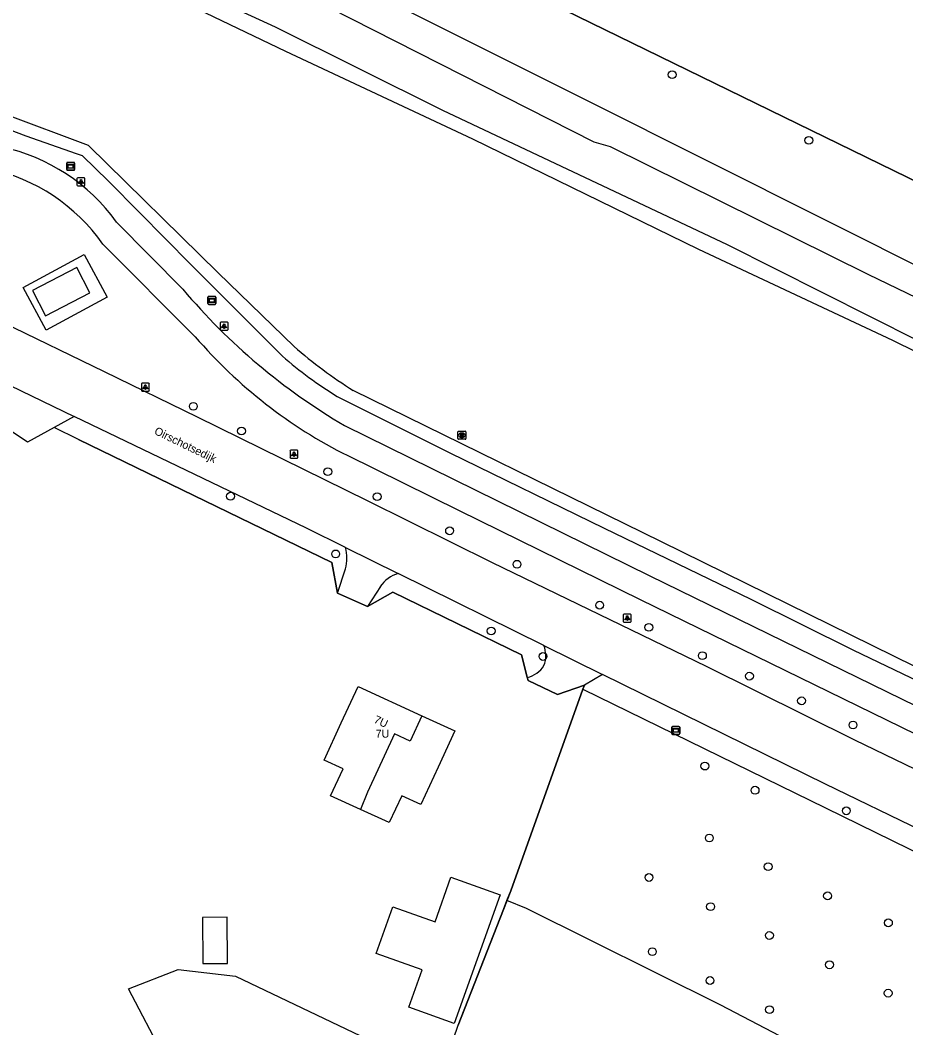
# Model space of a CAD drawing. Extents: x 156141 to 158132, y 385651 to 388399.
# Drawn here: x 156399.4 to 156510, y 386384.2 to 386510.1 of the extents above; entities that cross this region are included whole.
import ezdxf

# ---------------------------------------------------------------- set-up
doc = ezdxf.new("R2010")
doc.units = 0
for name, color, linetype in [('IMGEO_Berm_groen', 7, 'Continuous'), ('IMGEO_Boom', 7, 'Continuous'), ('IMGEO_Bouwland', 7, 'Continuous'), ('IMGEO_Fietspad_gesloten', 7, 'Continuous'), ('IMGEO_Grasland_overig', 7, 'Continuous'), ('IMGEO_Groenvoorziening', 7, 'Continuous'), ('IMGEO_Hek', 7, 'Continuous'), ('IMGEO_Lichtpunt', 7, 'Continuous'), ('IMGEO_Loofbos', 7, 'Continuous'), ('IMGEO_Openbare_ruimte_label', 7, 'Continuous'), ('IMGEO_Pand', 7, 'Continuous'), ('IMGEO_Pand_nummerreeks', 7, 'Continuous'), ('IMGEO_Rijbaan_lokaal_gesloten', 7, 'Continuous'), ('IMGEO_Rijbaan_lokaal_open', 7, 'Continuous'), ('IMGEO_Rioolput', 7, 'Continuous'), ('IMGEO_Verklikker', 7, 'Continuous'), ('IMGEO_Voetpad_open', 7, 'Continuous'), ('IMGEO_Waterloop', 7, 'Continuous')]:
    doc.layers.add(name, color=color, linetype=linetype)

msp = doc.modelspace()

# ---------------------------------------------------------------- linework, layer by layer
at = {"layer": 'IMGEO_Berm_groen'}
for points in [[(156439.05, 386438.5), (156438.33, 386442.3), (156406.68, 386457.7), (156403.63, 386459.18)], [(156462.74, 386427.97), (156462.02, 386430.79), (156445.93, 386438.62), (156442.77, 386436.8)], [(156469.7, 386426.47), (156469.88, 386426.98)], [(156469.7, 386426.47), (156500, 386411.64), (156522.94, 386400.43), (156557.16, 386383.7), (156598.54, 386363.27), (156625.35, 386349.27), (156637.95, 386342.17)]]:
    msp.add_lwpolyline(points, dxfattribs=at)
at = {"layer": 'IMGEO_Boom'}
for centre in [(156480.85, 386503.28), (156497.93, 386495.07), (156421.02, 386461.84), (156427.04, 386458.75), (156437.82, 386453.67), (156425.67, 386450.6), (156443.99, 386450.55), (156453.04, 386446.28), (156438.8, 386443.39), (156461.47, 386442.1), (156471.79, 386436.98), (156458.24, 386433.76), (156477.94, 386434.21), (156464.71, 386430.58), (156484.63, 386430.67), (156490.51, 386428.12), (156497.02, 386425.04), (156503.45, 386422.01), (156484.94, 386416.88), (156491.21, 386413.86), (156502.61, 386411.29), (156485.49, 386407.89), (156492.84, 386404.31), (156477.95, 386402.96), (156500.27, 386400.66), (156485.65, 386399.31), (156507.87, 386397.29), (156493.01, 386395.71), (156478.38, 386393.68), (156500.51, 386392.05), (156485.58, 386390.08), (156507.84, 386388.5), (156493.02, 386386.44)]:
    msp.add_circle(centre, 0.489, dxfattribs=at)
at = {"layer": 'IMGEO_Bouwland'}
msp.add_lwpolyline([(156417.37, 386380.55), (156412.91, 386389.03), (156419.13, 386391.45), (156426.28, 386390.61), (156452.01, 386378.34), (156453, 386381.23), (156454.11, 386384.49), (156459.32, 386397.81), (156459.77, 386398.95), (156460.2, 386400.06)], dxfattribs=at)
at = {"layer": 'IMGEO_Fietspad_gesloten'}
for points in [[(156411.43, 386484.87), (156419.73, 386476.46)], [(156421.26, 386470.53), (156409.71, 386482.11)], [(156439.93, 386459.43), (156478.08, 386440.66), (156748.12, 386308.63)], [(156746.83, 386305.79), (156476.91, 386437.66), (156454.28, 386448.77), (156440.3, 386455.67)]]:
    msp.add_lwpolyline(points, dxfattribs=at)
for centre, radius, start, end in [((156391.92, 386470.71), 24.11, 35.9629, 77.5317), ((156390.63, 386468.7), 23.33, 35.087, 77.7389), ((156479.24, 386526.56), 77.79, 220.0905, 239.6437), ((156467.78, 386510.52), 61.34, 220.6876, 243.3947)]:
    msp.add_arc(centre, radius, start, end, dxfattribs=at)
at = {"layer": 'IMGEO_Grasland_overig'}
for points in [[(156460.2, 386400.06), (156460.68, 386401.29), (156469.7, 386426.47)], [(156628.11, 386317.67), (156606.62, 386328.01), (156593.06, 386334.88), (156583.4, 386339.46), (156570.36, 386346.01), (156559.71, 386351.24), (156550.14, 386355.98), (156542.93, 386359.58), (156531.52, 386364.75), (156519.92, 386370.3), (156509.11, 386375.43), (156486.95, 386387.02), (156462.63, 386399.06), (156460.2, 386400.06)]]:
    msp.add_lwpolyline(points, dxfattribs=at)
at = {"layer": 'IMGEO_Groenvoorziening'}
for points in [[(156371.99, 386566.95), (156447.85, 386532.48), (156458.65, 386520.98), (156467.27, 386511.43), (156654.66, 386420.01), (156654.6, 386419.89), (156819.39, 386339.6), (156839.51, 386329.8), (156877.29, 386311.4)], [(156658.9, 386407.79), (156570.45, 386449.76), (156500, 386485.09), (156470.28, 386500), (156436.29, 386517.05)]]:
    msp.add_lwpolyline(points, dxfattribs=at)
at = {"layer": 'IMGEO_Hek'}
for points in [[(156654.66, 386420.01), (156467.27, 386511.43), (156458.65, 386520.98)], [(156406.68, 386457.7), (156438.33, 386442.3), (156439.05, 386438.5)], [(156439.05, 386438.5), (156442.77, 386436.8)], [(156442.77, 386436.8), (156445.93, 386438.62), (156462.02, 386430.79), (156462.74, 386427.97)], [(156462.74, 386427.97), (156462.84, 386427.57), (156466.54, 386425.84), (156469.88, 386426.98)], [(156469.7, 386426.47), (156460.68, 386401.29)], [(156469.88, 386426.98), (156469.7, 386426.47)], [(156460.68, 386401.29), (156459.77, 386398.95)], [(156459.77, 386398.95), (156454.11, 386384.49)]]:
    msp.add_lwpolyline(points, dxfattribs=at)
at = {"layer": 'IMGEO_Lichtpunt'}
for p, q in [((156406.48, 386490.3), (156406.48, 386489.5)), ((156406.48, 386490.3), (156406.48, 386489.5)), ((156407.38, 386490.4), (156406.57, 386490.4)), ((156407.38, 386490.4), (156406.57, 386490.4)), ((156407.48, 386489.5), (156407.48, 386490.3)), ((156407.48, 386489.5), (156407.48, 386490.3)), ((156406.57, 386489.4), (156407.38, 386489.4)), ((156406.57, 386489.4), (156407.38, 386489.4)), ((156424.37, 386472.25), (156424.37, 386471.45)), ((156424.37, 386472.25), (156424.37, 386471.45)), ((156425.28, 386472.35), (156424.47, 386472.35)), ((156425.28, 386472.35), (156424.47, 386472.35)), ((156425.37, 386471.45), (156425.37, 386472.25)), ((156425.37, 386471.45), (156425.37, 386472.25)), ((156424.47, 386471.35), (156425.28, 386471.35)), ((156424.47, 386471.35), (156425.28, 386471.35)), ((156414.53, 386464.64), (156414.53, 386463.83)), ((156414.53, 386464.64), (156414.53, 386463.83)), ((156415.43, 386464.73), (156414.62, 386464.73)), ((156415.43, 386464.73), (156414.62, 386464.73)), ((156415.52, 386463.83), (156415.52, 386464.64)), ((156415.52, 386463.83), (156415.52, 386464.64)), ((156414.62, 386463.74), (156415.43, 386463.74)), ((156414.62, 386463.74), (156415.43, 386463.74)), ((156433.1, 386456.25), (156433.1, 386455.45)), ((156433.1, 386456.25), (156433.1, 386455.45)), ((156434, 386456.35), (156433.19, 386456.35)), ((156434, 386456.35), (156433.19, 386456.35)), ((156434.09, 386455.45), (156434.09, 386456.25)), ((156434.09, 386455.45), (156434.09, 386456.25)), ((156433.19, 386455.35), (156434, 386455.35)), ((156433.19, 386455.35), (156434, 386455.35)), ((156474.73, 386435.77), (156474.73, 386434.96)), ((156474.73, 386435.77), (156474.73, 386434.96)), ((156475.64, 386435.86), (156474.83, 386435.86)), ((156475.64, 386435.86), (156474.83, 386435.86)), ((156475.73, 386434.96), (156475.73, 386435.77)), ((156475.73, 386434.96), (156475.73, 386435.77)), ((156474.83, 386434.87), (156475.64, 386434.87)), ((156474.83, 386434.87), (156475.64, 386434.87))]:
    msp.add_line(p, q, dxfattribs=at)
for points in [[(156406.85, 386489.97), (156406.89, 386489.94), (156406.71, 386489.68), (156406.67, 386489.7), (156406.85, 386489.97)], [(156406.96, 386489.92), (156407, 386489.92), (156407, 386489.6), (156406.96, 386489.6), (156406.96, 386489.92)], [(156407.07, 386489.94), (156407.1, 386489.97), (156407.29, 386489.7), (156407.25, 386489.68), (156407.07, 386489.94)], [(156424.75, 386471.92), (156424.79, 386471.89), (156424.6, 386471.63), (156424.56, 386471.65), (156424.75, 386471.92)], [(156424.85, 386471.87), (156424.9, 386471.87), (156424.9, 386471.55), (156424.85, 386471.55), (156424.85, 386471.87)], [(156424.96, 386471.89), (156425, 386471.92), (156425.18, 386471.65), (156425.15, 386471.63), (156424.96, 386471.89)], [(156414.9, 386464.3), (156414.94, 386464.27), (156414.75, 386464.01), (156414.71, 386464.04), (156414.9, 386464.3)], [(156415, 386464.25), (156415.05, 386464.25), (156415.05, 386463.93), (156415, 386463.93), (156415, 386464.25)], [(156415.11, 386464.27), (156415.15, 386464.3), (156415.34, 386464.04), (156415.3, 386464.01), (156415.11, 386464.27)], [(156433.47, 386455.92), (156433.51, 386455.89), (156433.32, 386455.63), (156433.28, 386455.66), (156433.47, 386455.92)], [(156433.57, 386455.87), (156433.62, 386455.87), (156433.62, 386455.55), (156433.57, 386455.55), (156433.57, 386455.87)], [(156433.68, 386455.89), (156433.72, 386455.92), (156433.91, 386455.65), (156433.87, 386455.63), (156433.68, 386455.89)], [(156475.11, 386435.43), (156475.15, 386435.41), (156474.96, 386435.14), (156474.92, 386435.17), (156475.11, 386435.43)], [(156475.21, 386435.39), (156475.26, 386435.39), (156475.26, 386435.06), (156475.21, 386435.06), (156475.21, 386435.39)], [(156475.32, 386435.41), (156475.36, 386435.43), (156475.55, 386435.17), (156475.51, 386435.14), (156475.32, 386435.41)]]:
    msp.add_lwpolyline(points, dxfattribs=at)
for centre in [(156406.98, 386490.1), (156424.87, 386472.05), (156415.03, 386464.44), (156433.6, 386456.05), (156475.23, 386435.57)]:
    msp.add_circle(centre, 0.0994, dxfattribs=at)
for centre, start, end in [((156406.57, 386490.3), 90, 180), ((156406.57, 386490.3), 90, 180), ((156406.57, 386489.5), 180, 270), ((156406.57, 386489.5), 180, 270), ((156407.38, 386490.3), 0, 90), ((156407.38, 386490.3), 0, 90), ((156407.38, 386489.5), 270, 0), ((156407.38, 386489.5), 270, 360), ((156424.47, 386472.25), 90, 180), ((156424.47, 386472.25), 90, 180), ((156425.28, 386472.25), 0, 90), ((156425.28, 386472.25), 0, 90), ((156424.47, 386471.45), 180, 270), ((156424.47, 386471.45), 180, 270), ((156425.28, 386471.45), 270, 0), ((156425.28, 386471.45), 270, 360), ((156414.62, 386464.64), 90, 180), ((156414.62, 386464.64), 90, 180), ((156415.43, 386464.64), 0, 90), ((156415.43, 386464.64), 0, 90), ((156414.62, 386463.83), 180, 270), ((156414.62, 386463.83), 180, 270), ((156415.43, 386463.83), 270, 0), ((156415.43, 386463.83), 270, 360), ((156433.19, 386456.25), 90, 180), ((156433.19, 386456.25), 90, 180), ((156433.19, 386455.45), 180, 270), ((156433.19, 386455.45), 180, 270), ((156434, 386456.25), 0, 90), ((156434, 386456.25), 0, 90), ((156434, 386455.45), 270, 0), ((156434, 386455.45), 270, 360), ((156474.83, 386435.77), 90, 180), ((156474.83, 386435.77), 90, 180), ((156475.64, 386435.77), 0, 90), ((156475.64, 386435.77), 0, 90), ((156474.83, 386434.96), 180, 270), ((156474.83, 386434.96), 180, 270), ((156475.64, 386434.96), 270, 0), ((156475.64, 386434.96), 270, 360)]:
    msp.add_arc(centre, 0.0946, start, end, dxfattribs=at)
at = {"layer": 'IMGEO_Loofbos'}
msp.add_lwpolyline([(156376.23, 386532.82), (156380.53, 386530.67), (156394.61, 386524.34), (156410.55, 386516.78), (156432.52, 386506.23), (156455.92, 386495.25), (156484.14, 386481.46), (156508.4, 386470.1), (156535.15, 386456.9), (156542.2, 386453.22), (156548.5, 386449.94), (156550.89, 386448.79), (156551.8, 386448.5), (156552.29, 386448.09)], dxfattribs=at)
at = {"layer": 'IMGEO_Pand'}
for points in [[(156402.57, 386473.16), (156408.09, 386476.03), (156406.45, 386479.18), (156400.93, 386476.31), (156402.57, 386473.16)], [(156441.91, 386411.46), (156438.17, 386413.17), (156439.73, 386416.54), (156437.35, 386417.63), (156439.51, 386422.28), (156441.61, 386426.81), (156449.56, 386423.17)], [(156449.56, 386423.17), (156453.71, 386421.27), (156451.61, 386416.73), (156449.45, 386412.09), (156447.07, 386413.18), (156445.51, 386409.81), (156441.91, 386411.46)], [(156449.56, 386423.17), (156448.1, 386419.99), (156446.15, 386420.89), (156442.79, 386413.62), (156441.91, 386411.46)], [(156445.96, 386399.3), (156451.22, 386397.43), (156453.21, 386402.98), (156459.38, 386400.78), (156453.6, 386384.71), (156447.96, 386386.73), (156449.62, 386391.4), (156443.87, 386393.47), (156445.96, 386399.3)], [(156425.25, 386397.98), (156422.18, 386397.97), (156422.2, 386392.21), (156425.27, 386392.22), (156425.25, 386397.98)]]:
    msp.add_lwpolyline(points, dxfattribs=at)
at = {"layer": 'IMGEO_Rijbaan_lokaal_gesloten'}
for points in [[(156393.16, 386474.43), (156397.17, 386472.36), (156409.89, 386466.18), (156421.49, 386460.52), (156442.74, 386450.05), (156458.35, 386442.32), (156485.12, 386429.36), (156503.65, 386420.14), (156535.07, 386404.96), (156559.37, 386393.18), (156614.76, 386366.1), (156674.13, 386337.24), (156685.25, 386331.63), (156700.19, 386324.34), (156714.3, 386317.45), (156736.53, 386306.59), (156745.28, 386302.37)], [(156398.15, 386464.42), (156406.15, 386460.56)], [(156440.02, 386444.19), (156435.16, 386446.59), (156406.15, 386460.56)], [(156440.02, 386444.19), (156446.61, 386440.94)], [(156439.05, 386438.5), (156440.02, 386441.52)], [(156464.82, 386431.96), (156446.61, 386440.94)], [(156444.39, 386439.33), (156442.77, 386436.8)], [(156442.77, 386436.8), (156439.05, 386438.5)], [(156464.82, 386431.96), (156472.16, 386428.34)], [(156469.88, 386426.98), (156466.54, 386425.84), (156462.84, 386427.57), (156462.74, 386427.97)], [(156472.16, 386428.34), (156469.88, 386426.98)], [(156742.53, 386296.33), (156535.86, 386397.24), (156524.08, 386402.95), (156500, 386414.61), (156472.16, 386428.34)]]:
    msp.add_lwpolyline(points, dxfattribs=at)
for centre, radius, start, end in [((156434.97, 386442.85), 5.23, 345.2217, 14.7783), ((156447.84, 386436.91), 4.22, 107.0304, 144.9444), ((156461.55, 386430.68), 3.51, 339.4615, 21.4498), ((156462.08, 386431.13), 3.23, 281.6662, 328.5007)]:
    msp.add_arc(centre, radius, start, end, dxfattribs=at)
at = {"layer": 'IMGEO_Rijbaan_lokaal_open'}
for points in [[(156403.63, 386459.18), (156400.28, 386457.34), (156396.7, 386459.72), (156397.15, 386461.17)], [(156406.15, 386460.56), (156403.63, 386459.18)]]:
    msp.add_lwpolyline(points, dxfattribs=at)
at = {"layer": 'IMGEO_Rioolput'}
for p, q in [((156454.08, 386457.8), (156454.08, 386458.65)), ((156454.15, 386458.72), (156455, 386458.72)), ((156454.56, 386458.5), (156454.59, 386458.5)), ((156454.59, 386457.94), (156454.56, 386457.94)), ((156455.08, 386458.65), (156455.08, 386457.8)), ((156455, 386457.72), (156454.15, 386457.72))]:
    msp.add_line(p, q, dxfattribs=at)
for points in [[(156454.08, 386457.8), (156454.08, 386458.65)], [(156454.15, 386458.72), (156455, 386458.72)], [(156454.67, 386458.42), (156454.41, 386458.42), (156454.41, 386458.02)], [(156454.41, 386458.02), (156454.54, 386458.02), (156454.54, 386458.19), (156454.55, 386458.19)], [(156454.59, 386458.34), (156454.54, 386458.34), (156454.54, 386458.26)], [(156454.54, 386458.26), (156454.59, 386458.26)], [(156454.59, 386458.16), (156454.67, 386458.02), (156454.81, 386458.02), (156454.74, 386458.15)], [(156455.08, 386458.65), (156455.08, 386457.8)], [(156455, 386457.72), (156454.15, 386457.72)]]:
    msp.add_lwpolyline(points, dxfattribs=at)
for centre, radius, start, end in [((156454.15, 386458.65), 0.0765, 91.552, 178.448), ((156454.15, 386458.65), 0.0765, 91.552, 178.448), ((156454.55, 386458.13), 0.0533, 26.0293, 88.6989), ((156454.6, 386458.25), 0.0964, 77.0061, 93.1865), ((156454.57, 386458.45), 0.19, 274.7715, 282.9687), ((156454.61, 386458.3), 0.0378, 276.6634, 79.6772), ((156454.66, 386458.31), 0.109, 350.3612, 89.416), ((156454.66, 386458.31), 0.112, 277.5842, 350.9817), ((156454.65, 386458.1), 0.108, 29.5134, 73.7905), ((156455, 386458.65), 0.0765, 1.552, 88.448), ((156455, 386458.65), 0.0765, 1.552, 88.448), ((156454.15, 386457.8), 0.0765, 181.552, 268.448), ((156454.15, 386457.8), 0.0765, 181.552, 268.448), ((156455, 386457.8), 0.0765, 271.552, 358.448), ((156455, 386457.8), 0.0765, 271.552, 358.448)]:
    msp.add_arc(centre, radius, start, end, dxfattribs=at)
for centre, major_axis, ratio, start_param, end_param in [((156454.56, 386458.22), (-0.387, 0.002), 0.722429, 4.712389, 7.853982), ((156454.59, 386458.22), (-0.39, 0.002), 0.717154, 1.570796, 4.712389)]:
    msp.add_ellipse(centre, major_axis=major_axis, ratio=ratio, start_param=start_param, end_param=end_param, dxfattribs=at)
at = {"layer": 'IMGEO_Verklikker'}
for p, q in [((156405.2, 386491.43), (156405.2, 386492.22)), ((156405.2, 386492.22), (156405.2, 386491.43)), ((156405.3, 386492.32), (156406.09, 386492.32)), ((156406.09, 386492.32), (156405.3, 386492.32)), ((156406.19, 386492.22), (156406.19, 386491.43)), ((156406.19, 386491.43), (156406.19, 386492.22)), ((156406.09, 386491.33), (156405.3, 386491.33)), ((156405.3, 386491.33), (156406.09, 386491.33)), ((156422.94, 386475.57), (156423.73, 386475.57)), ((156423.73, 386475.57), (156422.94, 386475.57)), ((156422.84, 386474.67), (156422.84, 386475.47)), ((156422.84, 386475.47), (156422.84, 386474.67)), ((156423.73, 386474.57), (156422.94, 386474.57)), ((156422.94, 386474.57), (156423.73, 386474.57)), ((156423.83, 386475.47), (156423.83, 386474.67)), ((156423.83, 386474.67), (156423.83, 386475.47)), ((156480.8, 386420.93), (156480.8, 386421.73)), ((156480.8, 386421.73), (156480.8, 386420.93)), ((156480.9, 386421.83), (156481.69, 386421.83)), ((156481.69, 386421.83), (156480.9, 386421.83)), ((156481.79, 386421.73), (156481.79, 386420.93)), ((156481.79, 386420.93), (156481.79, 386421.73)), ((156481.69, 386420.83), (156480.9, 386420.83)), ((156480.9, 386420.83), (156481.69, 386420.83))]:
    msp.add_line(p, q, dxfattribs=at)
for points in [[(156405.3, 386492.06), (156406.09, 386492.06), (156406.09, 386491.59), (156405.3, 386491.59), (156405.3, 386492.06)], [(156405.36, 386491.99), (156405.36, 386491.66), (156406.02, 386491.66), (156406.02, 386491.99), (156405.36, 386491.99)], [(156422.94, 386475.3), (156423.73, 386475.3), (156423.73, 386474.83), (156422.94, 386474.83), (156422.94, 386475.3)], [(156423, 386475.23), (156423, 386474.9), (156423.66, 386474.9), (156423.66, 386475.23), (156423, 386475.23)], [(156480.91, 386421.56), (156481.69, 386421.56), (156481.69, 386421.1), (156480.91, 386421.1), (156480.91, 386421.56)], [(156480.97, 386421.5), (156480.97, 386421.16), (156481.63, 386421.16), (156481.63, 386421.5), (156480.97, 386421.5)]]:
    msp.add_lwpolyline(points, dxfattribs=at)
for centre, start, end in [((156405.3, 386492.22), 90, 180), ((156405.3, 386492.22), 90, 180), ((156406.09, 386492.22), 0, 90), ((156406.09, 386492.22), 360, 90), ((156405.3, 386491.43), 180, 270), ((156405.3, 386491.43), 180, 270), ((156406.09, 386491.43), 270, 0), ((156406.09, 386491.43), 270, 0), ((156422.94, 386475.47), 90, 180), ((156422.94, 386475.47), 90, 180), ((156423.73, 386475.47), 0, 90), ((156423.73, 386475.47), 360, 90), ((156422.94, 386474.67), 180, 270), ((156422.94, 386474.67), 180, 270), ((156423.73, 386474.67), 270, 0), ((156423.73, 386474.67), 270, 0), ((156480.9, 386421.73), 90, 180), ((156480.9, 386421.73), 90, 180), ((156481.69, 386421.73), 0, 90), ((156481.69, 386421.73), 360, 90), ((156480.9, 386420.93), 180, 270), ((156480.9, 386420.93), 180, 270), ((156481.69, 386420.93), 270, 0), ((156481.69, 386420.93), 270, 0)]:
    msp.add_arc(centre, 0.1, start, end, dxfattribs=at)
at = {"layer": 'IMGEO_Voetpad_open'}
for points in [[(156433.61, 386469.3), (156424.13, 386478.53), (156407.94, 386494.45), (156376.51, 386506.18), (156366.42, 386509.94)], [(156363.23, 386506.56), (156366.48, 386508.27), (156375.27, 386505.03), (156393.6, 386498.1), (156400.09, 386495.65), (156406.4, 386493.42), (156407.14, 386493.16), (156410.43, 386489.99), (156414.3, 386486.07), (156420.71, 386479.58), (156432.15, 386468.1)], [(156410.25, 386475.48), (156402.63, 386471.36), (156399.76, 386476.67), (156407.39, 386480.79), (156410.25, 386475.48)], [(156439.01, 386463.07), (156453.09, 386456.04), (156472.35, 386446.61), (156490.68, 386437.75), (156503.51, 386431.38), (156514.71, 386425.98), (156539.43, 386413.93), (156543.35, 386412.02), (156558.18, 386404.76), (156574.82, 386396.59), (156609.28, 386379.8), (156613.05, 386377.82), (156629.2, 386369.96)], [(157000, 386190.5), (156998.62, 386191.17), (156997.02, 386191.93), (156993.26, 386193.78), (156878.47, 386250), (156816.86, 386279.93), (156794.45, 386290.97), (156728.15, 386323.33), (156696.62, 386338.78), (156663.58, 386354.86), (156633.35, 386369.63), (156571.02, 386399.96), (156546.07, 386412.38), (156540.12, 386415.26), (156513.81, 386428.04), (156479.51, 386444.91), (156441.01, 386463.8)]]:
    msp.add_lwpolyline(points, dxfattribs=at)
for centre, radius, start, end in [((156477.52, 386520.63), 67.55, 229.4548, 237.2826), ((156464.24, 386504.64), 48.62, 228.7048, 238.7361)]:
    msp.add_arc(centre, radius, start, end, dxfattribs=at)
at = {"layer": 'IMGEO_Waterloop'}
for points in [[(156560.01, 386451.66), (156540.44, 386461.36), (156505.36, 386478.31), (156473.14, 386494.28), (156471.12, 386494.85), (156429.81, 386515.83), (156394.59, 386533.14), (156377.09, 386541.78), (156375.83, 386542.6), (156369.37, 386548.15)], [(156365.21, 386544.46), (156373.03, 386537.62), (156381.18, 386532.98), (156412.89, 386517.71), (156431.25, 386509.24), (156452.14, 386498.84), (156487.74, 386482.07), (156517.52, 386467.08), (156541.04, 386455.61), (156552.61, 386449.52)]]:
    msp.add_lwpolyline(points, dxfattribs=at)

# ---------------------------------------------------------------- texts
at = {"layer": 'IMGEO_Openbare_ruimte_label'}
msp.add_text('Oirschotsedijk', height=1, rotation=334.0243, dxfattribs=at).set_placement((156416.05, 386458.42))
at = {"layer": 'IMGEO_Pand_nummerreeks'}
msp.add_text('7U', height=1, rotation=335.3833, dxfattribs=at).set_placement((156443.49, 386422.34))
msp.add_text('7U', height=1, dxfattribs=at).set_placement((156443.8, 386420.43))

doc.saveas('drawing.dxf')
